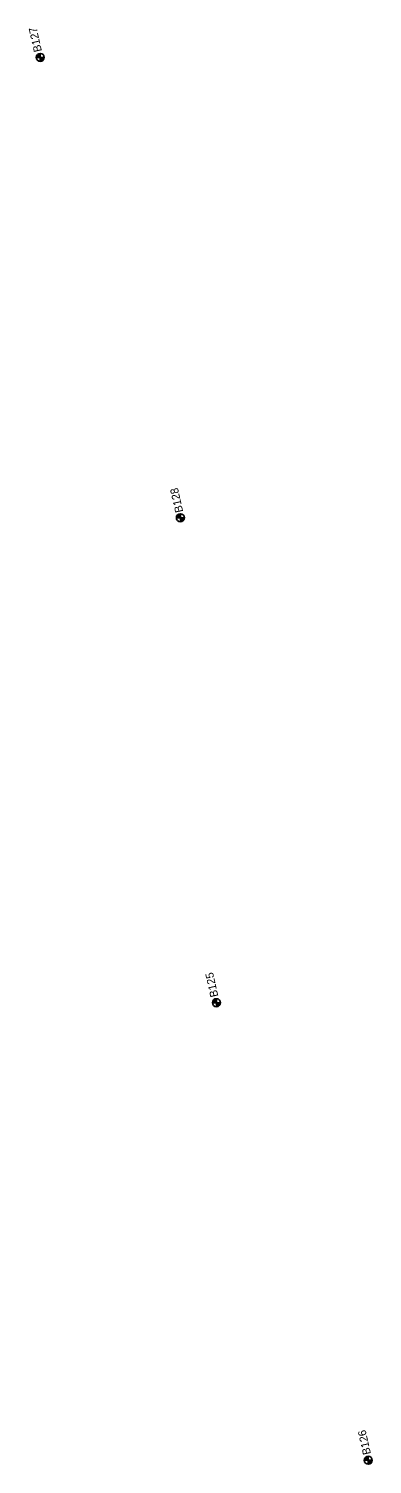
# Model space of a CAD drawing. Extents: x 311409 to 379449, y 121539 to 224848.
# Drawn here: x 356130 to 356559, y 197719 to 199512 of the extents above; entities that cross this region are included whole.
import ezdxf

# ---------------------------------------------------------------- set-up
doc = ezdxf.new("R2010")
doc.units = 0
for name, color, linetype in [('E_SOIL_BORE1 [KAPUR_CADDS_LEVELS]', 7, 'Continuous'), ('E_SOIL_BORE2 [KAPUR_CADDS_LEVELS]', 7, 'Continuous'), ('P_MARK', 7, 'Continuous')]:
    doc.layers.add(name, color=color, linetype=linetype)

msp = doc.modelspace()

# ---------------------------------------------------------------- linework, layer by layer
at = {"layer": 'P_MARK'}
for p, q in [((356139.4, 199476.4), (356149.4, 199476.4)), ((356144.4, 199481.4), (356144.4, 199471.4)), ((356314.3, 198901.3), (356324.3, 198901.3)), ((356319.3, 198906.3), (356319.3, 198896.3)), ((356359.4, 198295.4), (356369.4, 198295.4)), ((356364.4, 198300.4), (356364.4, 198290.4)), ((356548.9, 197723.7), (356558.9, 197723.7)), ((356553.9, 197728.7), (356553.9, 197718.7))]:
    msp.add_line(p, q, dxfattribs=at)
for centre in [(356144.4, 199476.4), (356319.3, 198901.3), (356364.4, 198295.4), (356553.9, 197723.7)]:
    msp.add_circle(centre, 5, dxfattribs=at)
for centre, radius, start, end in [((356144.4, 199476.4), 4.5, 89.9869, 179.9869), ((356144.4, 199476.4), 4, 89.9869, 179.9869), ((356144.4, 199476.4), 3.5, 89.9869, 179.9869), ((356144.4, 199476.4), 3, 89.9869, 179.9869), ((356144.4, 199476.4), 2.5, 89.9869, 179.9869), ((356144.4, 199476.4), 2, 89.9869, 179.9869), ((356144.4, 199476.4), 1.5, 89.9869, 179.9869), ((356144.4, 199476.4), 1, 89.9869, 179.9869), ((356144.4, 199476.4), 0.5, 89.9869, 179.9869), ((356144.4, 199476.4), 4.5, 269.9869, 359.9869), ((356144.4, 199476.4), 4, 269.9869, 359.9869), ((356144.4, 199476.4), 3.5, 269.9869, 359.9869), ((356144.4, 199476.4), 3, 269.9869, 359.9869), ((356144.4, 199476.4), 2.5, 269.9869, 359.9869), ((356144.4, 199476.4), 2, 269.9869, 359.9869), ((356144.4, 199476.4), 1.5, 269.9869, 359.9869), ((356144.4, 199476.4), 1, 269.9869, 359.9869), ((356144.4, 199476.4), 0.5, 269.9869, 359.9869), ((356319.3, 198901.3), 4.5, 89.9869, 179.9869), ((356319.3, 198901.3), 4, 89.9869, 179.9869), ((356319.3, 198901.3), 3.5, 89.9869, 179.9869), ((356319.3, 198901.3), 3, 89.9869, 179.9869), ((356319.3, 198901.3), 2.5, 89.9869, 179.9869), ((356319.3, 198901.3), 2, 89.9869, 179.9869), ((356319.3, 198901.3), 1.5, 89.9869, 179.9869), ((356319.3, 198901.3), 1, 89.9869, 179.9869), ((356319.3, 198901.3), 0.5, 89.9869, 179.9869), ((356319.3, 198901.3), 4.5, 269.9869, 359.9869), ((356319.3, 198901.3), 4, 269.9869, 359.9869), ((356319.3, 198901.3), 3.5, 269.9869, 359.9869), ((356319.3, 198901.3), 3, 269.9869, 359.9869), ((356319.3, 198901.3), 2.5, 269.9869, 359.9869), ((356319.3, 198901.3), 2, 269.9869, 359.9869), ((356319.3, 198901.3), 1.5, 269.9869, 359.9869), ((356319.3, 198901.3), 1, 269.9869, 359.9869), ((356319.3, 198901.3), 0.5, 269.9869, 359.9869), ((356364.4, 198295.4), 4.5, 89.9869, 179.9869), ((356364.4, 198295.4), 4, 89.9869, 179.9869), ((356364.4, 198295.4), 3.5, 89.9869, 179.9869), ((356364.4, 198295.4), 3, 89.9869, 179.9869), ((356364.4, 198295.4), 2.5, 89.9869, 179.9869), ((356364.4, 198295.4), 2, 89.9869, 179.9869), ((356364.4, 198295.4), 1.5, 89.9869, 179.9869), ((356364.4, 198295.4), 1, 89.9869, 179.9869), ((356364.4, 198295.4), 0.5, 89.9869, 179.9869), ((356364.4, 198295.4), 4.5, 269.9869, 359.9869), ((356364.4, 198295.4), 4, 269.9869, 359.9869), ((356364.4, 198295.4), 3.5, 269.9869, 359.9869), ((356364.4, 198295.4), 3, 269.9869, 359.9869), ((356364.4, 198295.4), 2.5, 269.9869, 359.9869), ((356364.4, 198295.4), 2, 269.9869, 359.9869), ((356364.4, 198295.4), 1.5, 269.9869, 359.9869), ((356364.4, 198295.4), 1, 269.9869, 359.9869), ((356364.4, 198295.4), 0.5, 269.9869, 359.9869), ((356553.9, 197723.7), 4.5, 89.9869, 179.9869), ((356553.9, 197723.7), 4, 89.9869, 179.9869), ((356553.9, 197723.7), 3.5, 89.9869, 179.9869), ((356553.9, 197723.7), 3, 89.9869, 179.9869), ((356553.9, 197723.7), 2.5, 89.9869, 179.9869), ((356553.9, 197723.7), 2, 89.9869, 179.9869), ((356553.9, 197723.7), 1.5, 89.9869, 179.9869), ((356553.9, 197723.7), 1, 89.9869, 179.9869), ((356553.9, 197723.7), 0.5, 89.9869, 179.9869), ((356553.9, 197723.7), 4.5, 269.9869, 359.9869), ((356553.9, 197723.7), 4, 269.9869, 359.9869), ((356553.9, 197723.7), 3.5, 269.9869, 359.9869), ((356553.9, 197723.7), 3, 269.9869, 359.9869), ((356553.9, 197723.7), 2.5, 269.9869, 359.9869), ((356553.9, 197723.7), 2, 269.9869, 359.9869), ((356553.9, 197723.7), 1.5, 269.9869, 359.9869), ((356553.9, 197723.7), 1, 269.9869, 359.9869), ((356553.9, 197723.7), 0.5, 269.9869, 359.9869)]:
    msp.add_arc(centre, radius, start, end, dxfattribs=at)

# ---------------------------------------------------------------- texts
at = {"layer": 'E_SOIL_BORE1 [KAPUR_CADDS_LEVELS]'}
for s, p in [('B127', (356146.5, 199484.4)), ('B128', (356322.9, 198908.9)), ('B125', (356366.8, 198303.5))]:
    msp.add_text(s, height=10, rotation=102.6348, dxfattribs=at).set_placement(p)
at = {"layer": 'E_SOIL_BORE2 [KAPUR_CADDS_LEVELS]'}
msp.add_text('B126', height=10, rotation=102.6348, dxfattribs=at).set_placement((356557.3, 197731.8))

doc.saveas('drawing.dxf')
